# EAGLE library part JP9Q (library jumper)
JUMPER
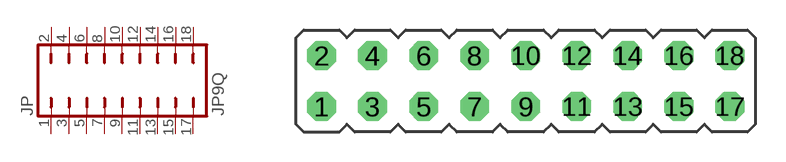
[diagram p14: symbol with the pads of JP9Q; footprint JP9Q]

Designator prefix JP

## JP9Q  [JP9Q]
1  1  pas
2  2  pas
3  3  pas
4  4  pas
5  5  pas
6  6  pas
7  7  pas
8  8  pas
9  9  pas
10  10  pas
11  11  pas
12  12  pas
13  13  pas
14  14  pas
15  15  pas
16  16  pas
17  17  pas
18  18  pas

## Footprint JP9Q (pad centres in mm)
JUMPER
drill 0.914 octagon: 1 -10.16,-1.27; 2 -10.16,1.27; 3 -7.62,-1.27; 4 -7.62,1.27; 5 -5.08,-1.27; 6 -5.08,1.27; 7 -2.54,-1.27; 8 -2.54,1.27; 9 0,-1.27; 10 0,1.27; 11 2.54,-1.27; 12 2.54,1.27; 13 5.08,-1.27; 14 5.08,1.27; 15 7.62,-1.27; 16 7.62,1.27; 17 10.16,-1.27; 18 10.16,1.27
